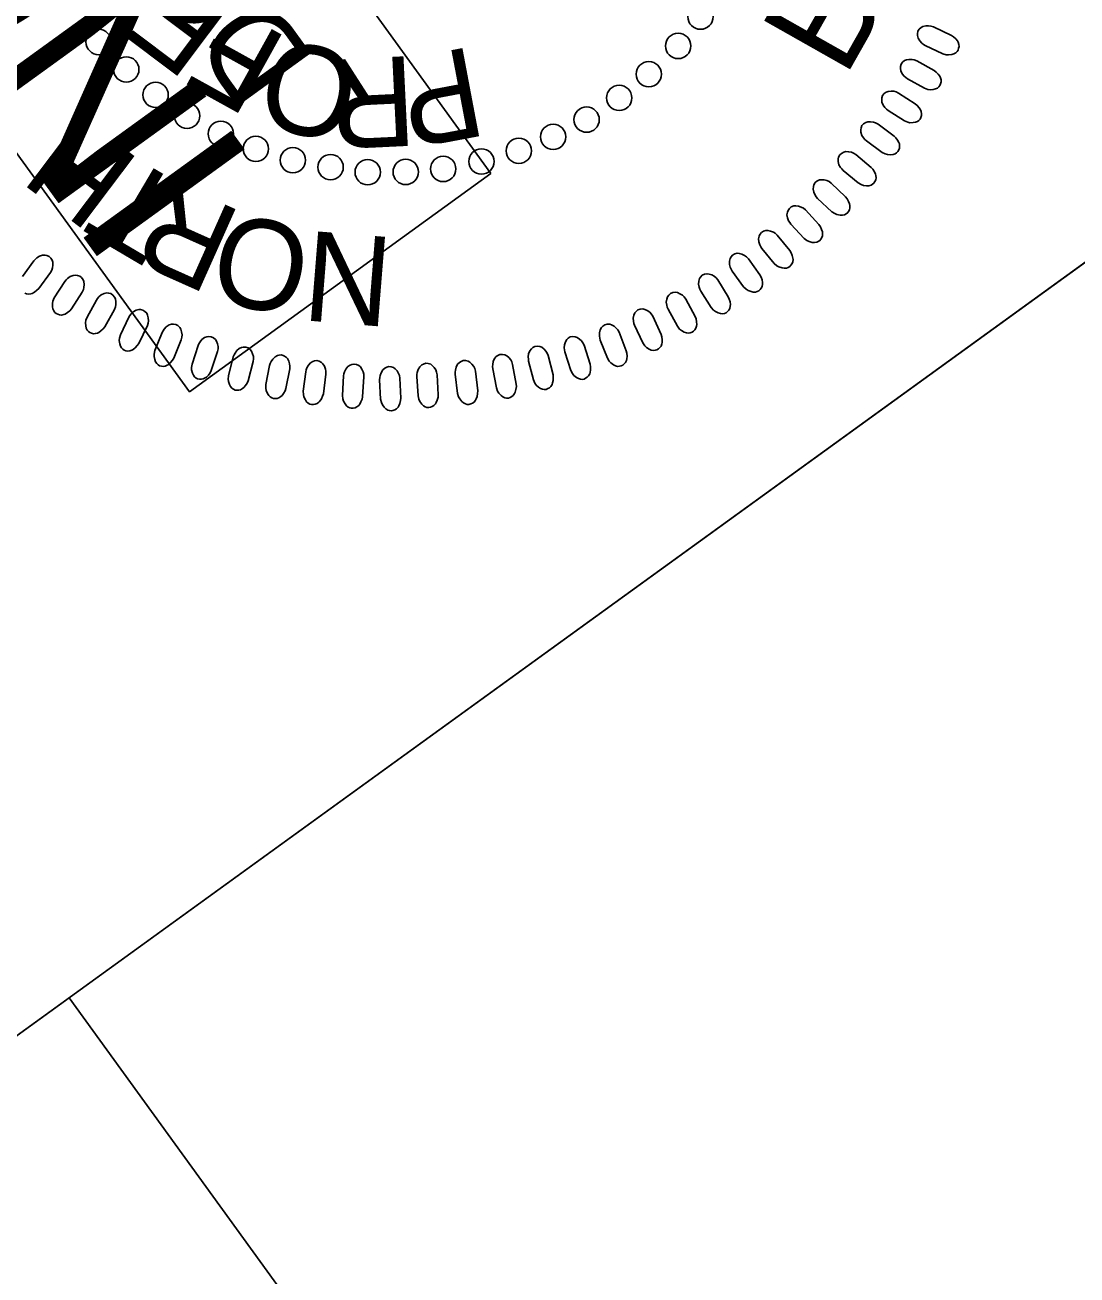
# Model space of a CAD drawing. Extents: x 474248 to 476123, y 501895 to 503900.
# Drawn here: x 474424.9 to 474491.3, y 503102.6 to 503181.5 of the extents above; entities that cross this region are included whole.
import ezdxf

# ---------------------------------------------------------------- set-up
doc = ezdxf.new("R2010")
doc.units = 0
for name, color, linetype in [('Prop Grid Mask', 7, 'Continuous'), ('Scratch_Level_5', 7, 'Continuous'), ('Sheet Layout Plan Border', 7, 'Continuous'), ('Sheet PE Seal Cell', 7, 'Continuous'), ('Sheet Plan CELL', 7, 'Continuous'), ('Sheet Sticker Incomplete CELL', 7, 'Continuous')]:
    doc.layers.add(name, color=color, linetype=linetype)

msp = doc.modelspace()

# ---------------------------------------------------------------- linework, layer by layer
at = {"layer": 'Prop Grid Mask'}
msp.add_lwpolyline([(474393.918, 503095.623), (474486.211, 502968.161), (474519.992, 502992.621), (474427.7, 503120.083)], close=True, dxfattribs=at)
at = {"layer": 'Scratch_Level_5'}
msp.add_lwpolyline([(474627.913, 502772.461), (474393.918, 503095.623), (474534.481, 503197.416), (474417.163, 503359.44), (475062.239, 503826.524), (475162.267, 503688.379), (475227.085, 503735.313), (475493.156, 503367.85)], close=True, dxfattribs=at)
at = {"layer": 'Sheet Layout Plan Border'}
msp.add_lwpolyline([(475148.793, 502314.888), (475799.674, 502786.065), (475874.954, 502840.561), (475397.529, 503499.918), (475353.895, 503468.323), (475265.228, 503590.778), (475283.66, 503604.124), (475199.913, 503719.785), (475161.571, 503692.033), (475161.571, 503692.033), (475161.571, 503692.033), (475161.571, 503692.033), (475161.571, 503692.033), (475063.524, 503827.461), (474417.163, 503359.44), (474534.481, 503197.416), (474393.908, 503095.616), (475024.421, 502224.855)], close=True, dxfattribs=at)
at = {"layer": 'Sheet PE Seal Cell'}
for points in [[(474481.763, 503180.24), (474482.873, 503179.715), (474483.086, 503179.655), (474483.235, 503179.643), (474483.436, 503179.671), (474483.578, 503179.713), (474483.697, 503179.78), (474483.778, 503179.857), (474483.844, 503179.95), (474483.874, 503180.06), (474483.898, 503180.181), (474483.889, 503180.301), (474483.843, 503180.438), (474483.797, 503180.527), (474483.69, 503180.651), (474483.553, 503180.782), (474483.419, 503180.871), (474482.286, 503181.415), (474482.123, 503181.467), (474481.978, 503181.486), (474481.795, 503181.473), (474481.622, 503181.431), (474481.507, 503181.378), (474481.387, 503181.261), (474481.304, 503181.134), (474481.277, 503180.982), (474481.277, 503180.866), (474481.312, 503180.709), (474481.415, 503180.529), (474481.548, 503180.391), (474481.653, 503180.309)], [(474480.637, 503178.131), (474481.711, 503177.538), (474481.921, 503177.465), (474482.069, 503177.443), (474482.271, 503177.46), (474482.415, 503177.491), (474482.539, 503177.551), (474482.624, 503177.623), (474482.696, 503177.712), (474482.732, 503177.819), (474482.764, 503177.939), (474482.762, 503178.059), (474482.725, 503178.199), (474482.685, 503178.29), (474482.586, 503178.421), (474482.458, 503178.56), (474482.329, 503178.657), (474481.233, 503179.272), (474481.073, 503179.334), (474480.93, 503179.362), (474480.747, 503179.36), (474480.57, 503179.33), (474480.453, 503179.283), (474480.325, 503179.175), (474480.235, 503179.053), (474480.198, 503178.904), (474480.191, 503178.787), (474480.216, 503178.628), (474480.308, 503178.442), (474480.432, 503178.296), (474480.531, 503178.207)], [(474479.416, 503176.137), (474480.45, 503175.477), (474480.656, 503175.39), (474480.801, 503175.359), (474481.004, 503175.363), (474481.149, 503175.386), (474481.277, 503175.438), (474481.366, 503175.504), (474481.444, 503175.588), (474481.487, 503175.693), (474481.526, 503175.81), (474481.532, 503175.93), (474481.504, 503176.072), (474481.469, 503176.166), (474481.379, 503176.303), (474481.26, 503176.449), (474481.137, 503176.554), (474480.082, 503177.236), (474479.926, 503177.309), (474479.785, 503177.346), (474479.602, 503177.356), (474479.424, 503177.336), (474479.304, 503177.297), (474479.169, 503177.197), (474479.072, 503177.081), (474479.026, 503176.935), (474479.012, 503176.819), (474479.027, 503176.658), (474479.107, 503176.467), (474479.221, 503176.313), (474479.315, 503176.219)], [(474478.049, 503174.21), (474479.04, 503173.487), (474479.239, 503173.388), (474479.382, 503173.347), (474479.586, 503173.338), (474479.732, 503173.352), (474479.862, 503173.396), (474479.956, 503173.457), (474480.038, 503173.535), (474480.087, 503173.638), (474480.134, 503173.752), (474480.148, 503173.872), (474480.128, 503174.015), (474480.1, 503174.11), (474480.018, 503174.253), (474479.908, 503174.407), (474479.793, 503174.519), (474478.782, 503175.266), (474478.632, 503175.347), (474478.492, 503175.394), (474478.311, 503175.415), (474478.132, 503175.407), (474478.01, 503175.376), (474477.87, 503175.284), (474477.765, 503175.175), (474477.709, 503175.031), (474477.688, 503174.917), (474477.693, 503174.756), (474477.76, 503174.559), (474477.865, 503174.399), (474477.953, 503174.298)], [(474476.582, 503172.341), (474477.526, 503171.557), (474477.718, 503171.446), (474477.859, 503171.396), (474478.061, 503171.374), (474478.208, 503171.379), (474478.341, 503171.415), (474478.438, 503171.47), (474478.525, 503171.543), (474478.581, 503171.642), (474478.634, 503171.753), (474478.656, 503171.871), (474478.646, 503172.016), (474478.623, 503172.113), (474478.551, 503172.26), (474478.45, 503172.421), (474478.342, 503172.54), (474477.381, 503173.349), (474477.236, 503173.44), (474477.1, 503173.494), (474476.92, 503173.527), (474476.741, 503173.531), (474476.618, 503173.507), (474476.471, 503173.424), (474476.36, 503173.322), (474476.295, 503173.182), (474476.267, 503173.069), (474476.262, 503172.908), (474476.316, 503172.708), (474476.411, 503172.54), (474476.492, 503172.435)], [(474474.967, 503170.58), (474475.859, 503169.738), (474476.045, 503169.615), (474476.182, 503169.556), (474476.383, 503169.522), (474476.529, 503169.517), (474476.664, 503169.544), (474476.764, 503169.593), (474476.856, 503169.661), (474476.918, 503169.756), (474476.978, 503169.864), (474477.007, 503169.981), (474477.006, 503170.126), (474476.989, 503170.224), (474476.927, 503170.376), (474476.837, 503170.542), (474476.736, 503170.668), (474475.827, 503171.535), (474475.688, 503171.635), (474475.556, 503171.699), (474475.379, 503171.742), (474475.2, 503171.757), (474475.075, 503171.741), (474474.924, 503171.668), (474474.807, 503171.572), (474474.733, 503171.437), (474474.698, 503171.326), (474474.683, 503171.165), (474474.725, 503170.962), (474474.809, 503170.789), (474474.883, 503170.68)], [(474473.279, 503168.946), (474474.117, 503168.05), (474474.294, 503167.916), (474474.427, 503167.848), (474474.625, 503167.802), (474474.771, 503167.788), (474474.908, 503167.806), (474475.011, 503167.849), (474475.107, 503167.911), (474475.175, 503168.002), (474475.242, 503168.105), (474475.278, 503168.22), (474475.285, 503168.365), (474475.275, 503168.464), (474475.222, 503168.619), (474475.143, 503168.791), (474475.05, 503168.923), (474474.197, 503169.846), (474474.065, 503169.954), (474473.937, 503170.026), (474473.763, 503170.081), (474473.586, 503170.107), (474473.46, 503170.099), (474473.304, 503170.035), (474473.182, 503169.947), (474473.1, 503169.816), (474473.057, 503169.708), (474473.032, 503169.548), (474473.061, 503169.343), (474473.135, 503169.166), (474473.201, 503169.051)], [(474471.447, 503167.416), (474472.227, 503166.469), (474472.395, 503166.324), (474472.524, 503166.249), (474472.719, 503166.189), (474472.864, 503166.166), (474473.001, 503166.176), (474473.107, 503166.212), (474473.206, 503166.269), (474473.279, 503166.355), (474473.353, 503166.455), (474473.396, 503166.566), (474473.413, 503166.71), (474473.409, 503166.81), (474473.365, 503166.968), (474473.297, 503167.145), (474473.214, 503167.282), (474472.42, 503168.257), (474472.294, 503168.373), (474472.171, 503168.452), (474472, 503168.518), (474471.825, 503168.555), (474471.7, 503168.555), (474471.54, 503168.501), (474471.412, 503168.421), (474471.322, 503168.295), (474471.273, 503168.19), (474471.239, 503168.033), (474471.254, 503167.826), (474471.316, 503167.644), (474471.376, 503167.525)], [(474469.568, 503165.991), (474470.287, 503164.997), (474470.446, 503164.842), (474470.57, 503164.758), (474470.76, 503164.687), (474470.903, 503164.655), (474471.041, 503164.657), (474471.149, 503164.686), (474471.252, 503164.735), (474471.33, 503164.817), (474471.41, 503164.911), (474471.46, 503165.021), (474471.486, 503165.163), (474471.488, 503165.263), (474471.455, 503165.424), (474471.398, 503165.604), (474471.322, 503165.746), (474470.592, 503166.769), (474470.475, 503166.893), (474470.356, 503166.98), (474470.19, 503167.056), (474470.017, 503167.104), (474469.892, 503167.112), (474469.729, 503167.068), (474469.596, 503166.997), (474469.499, 503166.876), (474469.444, 503166.775), (474469.398, 503166.62), (474469.401, 503166.412), (474469.452, 503166.227), (474469.504, 503166.105)], [(474427.415, 503165.326), (474426.755, 503164.292), (474426.669, 503164.086), (474426.637, 503163.941), (474426.641, 503163.737), (474426.664, 503163.593), (474426.716, 503163.466), (474426.783, 503163.375), (474426.867, 503163.299), (474426.972, 503163.255), (474427.089, 503163.216), (474427.209, 503163.21), (474427.351, 503163.238), (474427.444, 503163.273), (474427.582, 503163.363), (474427.728, 503163.482), (474427.833, 503163.604), (474428.515, 503164.66), (474428.587, 503164.815), (474428.624, 503164.957), (474428.634, 503165.14), (474428.615, 503165.318), (474428.576, 503165.438), (474428.476, 503165.573), (474428.36, 503165.669), (474428.213, 503165.716), (474428.098, 503165.73), (474427.937, 503165.715), (474427.745, 503165.637), (474427.591, 503165.52), (474427.497, 503165.427)], [(474467.587, 503164.718), (474468.242, 503163.681), (474468.391, 503163.515), (474468.51, 503163.425), (474468.695, 503163.341), (474468.836, 503163.3), (474468.973, 503163.293), (474469.083, 503163.315), (474469.189, 503163.358), (474469.272, 503163.435), (474469.358, 503163.525), (474469.415, 503163.63), (474469.45, 503163.771), (474469.458, 503163.87), (474469.435, 503164.033), (474469.39, 503164.216), (474469.323, 503164.363), (474468.658, 503165.43), (474468.549, 503165.561), (474468.436, 503165.655), (474468.275, 503165.742), (474468.106, 503165.8), (474467.981, 503165.816), (474467.816, 503165.782), (474467.679, 503165.719), (474467.575, 503165.606), (474467.512, 503165.508), (474467.458, 503165.356), (474467.448, 503165.149), (474467.486, 503164.96), (474467.531, 503164.835)], [(474429.412, 503164.158), (474428.819, 503163.084), (474428.746, 503162.875), (474428.724, 503162.727), (474428.739, 503162.524), (474428.772, 503162.381), (474428.831, 503162.257), (474428.904, 503162.171), (474428.992, 503162.1), (474429.1, 503162.063), (474429.219, 503162.031), (474429.339, 503162.033), (474429.48, 503162.07), (474429.57, 503162.111), (474429.702, 503162.209), (474429.841, 503162.338), (474429.938, 503162.466), (474430.551, 503163.562), (474430.614, 503163.722), (474430.642, 503163.866), (474430.64, 503164.049), (474430.61, 503164.226), (474430.564, 503164.342), (474430.455, 503164.47), (474430.334, 503164.56), (474430.184, 503164.597), (474430.068, 503164.604), (474429.909, 503164.579), (474429.722, 503164.488), (474429.576, 503164.364), (474429.487, 503164.264)], [(474465.521, 503163.575), (474466.11, 503162.499), (474466.247, 503162.325), (474466.36, 503162.227), (474466.54, 503162.132), (474466.678, 503162.082), (474466.815, 503162.066), (474466.926, 503162.082), (474467.034, 503162.118), (474467.122, 503162.189), (474467.213, 503162.273), (474467.276, 503162.376), (474467.32, 503162.514), (474467.334, 503162.612), (474467.321, 503162.776), (474467.288, 503162.962), (474467.231, 503163.113), (474466.634, 503164.219), (474466.533, 503164.357), (474466.427, 503164.457), (474466.272, 503164.554), (474466.106, 503164.623), (474465.982, 503164.646), (474465.816, 503164.624), (474465.675, 503164.569), (474465.563, 503164.462), (474465.495, 503164.368), (474465.432, 503164.22), (474465.408, 503164.014), (474465.436, 503163.824), (474465.472, 503163.696)], [(474431.455, 503163.066), (474430.93, 503161.956), (474430.87, 503161.742), (474430.857, 503161.594), (474430.886, 503161.392), (474430.927, 503161.252), (474430.994, 503161.132), (474431.072, 503161.051), (474431.165, 503160.985), (474431.274, 503160.955), (474431.396, 503160.931), (474431.516, 503160.94), (474431.653, 503160.986), (474431.741, 503161.032), (474431.866, 503161.138), (474431.997, 503161.275), (474432.086, 503161.41), (474432.63, 503162.543), (474432.682, 503162.705), (474432.701, 503162.851), (474432.688, 503163.033), (474432.646, 503163.208), (474432.593, 503163.321), (474432.476, 503163.443), (474432.35, 503163.524), (474432.198, 503163.552), (474432.082, 503163.552), (474431.924, 503163.516), (474431.744, 503163.414), (474431.606, 503163.281), (474431.524, 503163.176)], [(474463.4, 503162.559), (474463.92, 503161.448), (474464.046, 503161.265), (474464.153, 503161.16), (474464.327, 503161.054), (474464.461, 503160.996), (474464.597, 503160.971), (474464.708, 503160.98), (474464.818, 503161.009), (474464.911, 503161.075), (474465.007, 503161.153), (474465.076, 503161.251), (474465.128, 503161.386), (474465.149, 503161.483), (474465.147, 503161.648), (474465.125, 503161.836), (474465.077, 503161.989), (474464.551, 503163.131), (474464.459, 503163.275), (474464.359, 503163.382), (474464.21, 503163.488), (474464.05, 503163.568), (474463.928, 503163.598), (474463.76, 503163.586), (474463.616, 503163.541), (474463.497, 503163.441), (474463.424, 503163.352), (474463.351, 503163.208), (474463.315, 503163.004), (474463.33, 503162.812), (474463.358, 503162.682)], [(474433.563, 503162.101), (474433.109, 503160.961), (474433.062, 503160.743), (474433.059, 503160.595), (474433.1, 503160.396), (474433.15, 503160.258), (474433.225, 503160.143), (474433.307, 503160.066), (474433.404, 503160.007), (474433.516, 503159.983), (474433.638, 503159.967), (474433.757, 503159.984), (474433.891, 503160.038), (474433.977, 503160.09), (474434.095, 503160.204), (474434.216, 503160.349), (474434.297, 503160.489), (474434.768, 503161.653), (474434.81, 503161.819), (474434.82, 503161.966), (474434.796, 503162.147), (474434.743, 503162.318), (474434.683, 503162.428), (474434.559, 503162.542), (474434.427, 503162.615), (474434.274, 503162.634), (474434.158, 503162.626), (474434.003, 503162.581), (474433.829, 503162.467), (474433.7, 503162.325), (474433.625, 503162.216)], [(474461.24, 503161.627), (474461.69, 503160.485), (474461.805, 503160.295), (474461.904, 503160.183), (474462.071, 503160.067), (474462.201, 503160), (474462.335, 503159.967), (474462.447, 503159.969), (474462.559, 503159.991), (474462.656, 503160.05), (474462.756, 503160.122), (474462.832, 503160.216), (474462.892, 503160.347), (474462.919, 503160.443), (474462.927, 503160.608), (474462.916, 503160.796), (474462.879, 503160.953), (474462.426, 503162.125), (474462.343, 503162.275), (474462.25, 503162.388), (474462.108, 503162.503), (474461.953, 503162.592), (474461.833, 503162.631), (474461.665, 503162.63), (474461.518, 503162.593), (474461.394, 503162.501), (474461.315, 503162.416), (474461.233, 503162.277), (474461.184, 503162.076), (474461.187, 503161.884), (474461.207, 503161.752)], [(474435.833, 503161.275), (474435.452, 503160.109), (474435.419, 503159.889), (474435.425, 503159.74), (474435.479, 503159.544), (474435.538, 503159.409), (474435.619, 503159.299), (474435.706, 503159.228), (474435.807, 503159.175), (474435.919, 503159.158), (474436.042, 503159.15), (474436.16, 503159.174), (474436.291, 503159.236), (474436.373, 503159.293), (474436.483, 503159.415), (474436.596, 503159.567), (474436.667, 503159.711), (474437.065, 503160.903), (474437.096, 503161.072), (474437.097, 503161.219), (474437.061, 503161.398), (474436.998, 503161.565), (474436.931, 503161.672), (474436.8, 503161.777), (474436.664, 503161.842), (474436.509, 503161.851), (474436.395, 503161.836), (474436.243, 503161.781), (474436.076, 503161.657), (474435.956, 503161.507), (474435.888, 503161.393)], [(474459, 503160.874), (474459.377, 503159.707), (474459.48, 503159.51), (474459.572, 503159.392), (474459.731, 503159.265), (474459.858, 503159.191), (474459.989, 503159.15), (474460.1, 503159.144), (474460.213, 503159.16), (474460.314, 503159.213), (474460.419, 503159.278), (474460.499, 503159.367), (474460.569, 503159.494), (474460.601, 503159.589), (474460.619, 503159.752), (474460.621, 503159.94), (474460.593, 503160.099), (474460.215, 503161.298), (474460.141, 503161.452), (474460.055, 503161.571), (474459.921, 503161.695), (474459.772, 503161.793), (474459.654, 503161.841), (474459.487, 503161.849), (474459.338, 503161.822), (474459.208, 503161.738), (474459.125, 503161.658), (474459.033, 503161.525), (474458.972, 503161.326), (474458.963, 503161.135), (474458.975, 503161.002)], [(474438.061, 503160.566), (474437.754, 503159.378), (474437.735, 503159.157), (474437.75, 503159.009), (474437.817, 503158.817), (474437.883, 503158.686), (474437.971, 503158.58), (474438.063, 503158.516), (474438.167, 503158.469), (474438.281, 503158.46), (474438.403, 503158.459), (474438.52, 503158.49), (474438.646, 503158.561), (474438.724, 503158.623), (474438.827, 503158.751), (474438.93, 503158.909), (474438.992, 503159.059), (474439.314, 503160.273), (474439.334, 503160.443), (474439.326, 503160.589), (474439.279, 503160.766), (474439.205, 503160.929), (474439.131, 503161.031), (474438.994, 503161.128), (474438.854, 503161.185), (474438.7, 503161.183), (474438.586, 503161.162), (474438.438, 503161.097), (474438.28, 503160.963), (474438.17, 503160.806), (474438.108, 503160.688)], [(474440.356, 503160.021), (474440.124, 503158.816), (474440.119, 503158.594), (474440.143, 503158.446), (474440.222, 503158.259), (474440.296, 503158.133), (474440.391, 503158.033), (474440.487, 503157.974), (474440.593, 503157.933), (474440.707, 503157.932), (474440.83, 503157.939), (474440.944, 503157.977), (474441.066, 503158.056), (474441.14, 503158.122), (474441.234, 503158.257), (474441.326, 503158.422), (474441.379, 503158.573), (474441.624, 503159.807), (474441.634, 503159.977), (474441.616, 503160.122), (474441.559, 503160.296), (474441.475, 503160.455), (474441.395, 503160.552), (474441.252, 503160.64), (474441.108, 503160.688), (474440.955, 503160.677), (474440.842, 503160.648), (474440.698, 503160.574), (474440.549, 503160.431), (474440.449, 503160.267), (474440.395, 503160.145)], [(474454.446, 503159.818), (474454.674, 503158.613), (474454.751, 503158.404), (474454.828, 503158.276), (474454.97, 503158.131), (474455.086, 503158.041), (474455.211, 503157.983), (474455.321, 503157.963), (474455.435, 503157.965), (474455.541, 503158.005), (474455.653, 503158.057), (474455.745, 503158.134), (474455.829, 503158.252), (474455.873, 503158.342), (474455.911, 503158.501), (474455.937, 503158.689), (474455.93, 503158.85), (474455.704, 503160.087), (474455.65, 503160.248), (474455.58, 503160.377), (474455.463, 503160.517), (474455.326, 503160.634), (474455.217, 503160.694), (474455.051, 503160.724), (474454.9, 503160.716), (474454.761, 503160.649), (474454.667, 503160.58), (474454.561, 503160.459), (474454.475, 503160.27), (474454.442, 503160.082), (474454.437, 503159.948)], [(474456.713, 503160.3), (474457.016, 503159.111), (474457.107, 503158.908), (474457.191, 503158.785), (474457.342, 503158.648), (474457.463, 503158.566), (474457.591, 503158.517), (474457.703, 503158.504), (474457.817, 503158.512), (474457.92, 503158.559), (474458.029, 503158.618), (474458.115, 503158.701), (474458.192, 503158.824), (474458.231, 503158.916), (474458.259, 503159.078), (474458.272, 503159.266), (474458.255, 503159.427), (474457.952, 503160.646), (474457.888, 503160.804), (474457.81, 503160.929), (474457.684, 503161.061), (474457.541, 503161.169), (474457.427, 503161.223), (474457.26, 503161.242), (474457.111, 503161.224), (474456.976, 503161.149), (474456.886, 503161.074), (474456.787, 503160.947), (474456.714, 503160.753), (474456.693, 503160.562), (474456.696, 503160.429)], [(474442.634, 503159.618), (474442.478, 503158.402), (474442.488, 503158.179), (474442.521, 503158.034), (474442.611, 503157.851), (474442.693, 503157.73), (474442.795, 503157.637), (474442.893, 503157.584), (474443.002, 503157.55), (474443.115, 503157.555), (474443.238, 503157.57), (474443.349, 503157.616), (474443.466, 503157.701), (474443.535, 503157.773), (474443.622, 503157.913), (474443.703, 503158.083), (474443.747, 503158.238), (474443.914, 503159.484), (474443.913, 503159.655), (474443.886, 503159.799), (474443.817, 503159.969), (474443.724, 503160.121), (474443.638, 503160.213), (474443.49, 503160.293), (474443.344, 503160.331), (474443.191, 503160.31), (474443.081, 503160.275), (474442.942, 503160.192), (474442.801, 503160.039), (474442.712, 503159.869), (474442.666, 503159.745)], [(474445.028, 503159.359), (474444.948, 503158.135), (474444.972, 503157.914), (474445.014, 503157.771), (474445.115, 503157.594), (474445.205, 503157.479), (474445.312, 503157.392), (474445.414, 503157.346), (474445.525, 503157.318), (474445.638, 503157.331), (474445.759, 503157.353), (474445.867, 503157.405), (474445.978, 503157.498), (474446.043, 503157.574), (474446.12, 503157.719), (474446.191, 503157.895), (474446.224, 503158.052), (474446.313, 503159.306), (474446.302, 503159.476), (474446.266, 503159.618), (474446.186, 503159.784), (474446.084, 503159.93), (474445.991, 503160.016), (474445.839, 503160.086), (474445.692, 503160.115), (474445.539, 503160.085), (474445.432, 503160.042), (474445.298, 503159.951), (474445.168, 503159.79), (474445.089, 503159.615), (474445.051, 503159.487)], [(474447.301, 503159.122), (474447.365, 503157.898), (474447.415, 503157.68), (474447.474, 503157.544), (474447.595, 503157.38), (474447.698, 503157.276), (474447.814, 503157.203), (474447.92, 503157.168), (474448.034, 503157.154), (474448.145, 503157.18), (474448.262, 503157.217), (474448.364, 503157.281), (474448.463, 503157.386), (474448.519, 503157.469), (474448.578, 503157.622), (474448.628, 503157.805), (474448.642, 503157.965), (474448.583, 503159.22), (474448.552, 503159.389), (474448.499, 503159.525), (474448.401, 503159.68), (474448.282, 503159.813), (474448.18, 503159.888), (474448.021, 503159.939), (474447.871, 503159.951), (474447.723, 503159.904), (474447.622, 503159.848), (474447.5, 503159.742), (474447.39, 503159.567), (474447.332, 503159.384), (474447.309, 503159.253)], [(474449.651, 503159.325), (474449.726, 503158.101), (474449.777, 503157.884), (474449.837, 503157.748), (474449.959, 503157.585), (474450.063, 503157.481), (474450.18, 503157.409), (474450.287, 503157.375), (474450.4, 503157.362), (474450.511, 503157.389), (474450.628, 503157.426), (474450.729, 503157.492), (474450.827, 503157.598), (474450.883, 503157.681), (474450.941, 503157.835), (474450.989, 503158.018), (474451.002, 503158.178), (474450.933, 503159.433), (474450.9, 503159.601), (474450.847, 503159.738), (474450.748, 503159.891), (474450.627, 503160.024), (474450.526, 503160.098), (474450.365, 503160.148), (474450.214, 503160.158), (474450.068, 503160.11), (474449.966, 503160.054), (474449.845, 503159.946), (474449.737, 503159.77), (474449.68, 503159.587), (474449.658, 503159.455)], [(474452.076, 503159.471), (474452.227, 503158.253), (474452.291, 503158.04), (474452.36, 503157.908), (474452.492, 503157.754), (474452.603, 503157.657), (474452.723, 503157.591), (474452.832, 503157.565), (474452.946, 503157.559), (474453.054, 503157.593), (474453.17, 503157.637), (474453.266, 503157.709), (474453.357, 503157.821), (474453.407, 503157.907), (474453.456, 503158.064), (474453.493, 503158.25), (474453.495, 503158.411), (474453.348, 503159.659), (474453.305, 503159.824), (474453.243, 503159.957), (474453.134, 503160.105), (474453.006, 503160.23), (474452.899, 503160.297), (474452.736, 503160.337), (474452.585, 503160.338), (474452.442, 503160.28), (474452.344, 503160.218), (474452.23, 503160.103), (474452.133, 503159.92), (474452.088, 503159.734), (474452.074, 503159.601)]]:
    msp.add_lwpolyline(points, close=True, dxfattribs=at)
msp.add_lwpolyline([(474424.891, 503164.59), (474425.005, 503164.545), (474425.124, 503164.531), (474425.268, 503164.55), (474425.363, 503164.579), (474425.506, 503164.66), (474425.66, 503164.77), (474425.773, 503164.886), (474426.519, 503165.896), (474426.6, 503166.047), (474426.646, 503166.186), (474426.668, 503166.368), (474426.66, 503166.546), (474426.628, 503166.668), (474426.537, 503166.809), (474426.428, 503166.913), (474426.284, 503166.969), (474426.169, 503166.991), (474426.008, 503166.985), (474425.812, 503166.918), (474425.652, 503166.813), (474425.551, 503166.726), (474425.463, 503166.63), (474424.74, 503165.639)], dxfattribs=at)
for centre in [(474467.569, 503182.064), (474429.554, 503180.459), (474466.158, 503180.208), (474431.3, 503178.724), (474464.303, 503178.423), (474433.152, 503177.116), (474462.436, 503176.926), (474435.137, 503175.8), (474460.375, 503175.553), (474437.271, 503174.661), (474458.261, 503174.465), (474439.485, 503173.707), (474456.094, 503173.586), (474441.823, 503172.991), (474444.205, 503172.552), (474451.318, 503172.44), (474453.732, 503172.909), (474446.55, 503172.234), (474448.949, 503172.249)]:
    msp.add_circle(centre, 0.801, dxfattribs=at)
at = {"layer": 'Sheet Plan CELL'}
for points in [[(476006.781, 502658.499), (475156.352, 502042.692), (474393.908, 503095.616), (474515.447, 503183.634), (474398.139, 503345.665), (475127.058, 503873.458)], [(474424.343, 503117.653), (474365.666, 503198.69), (474456.797, 503264.676), (474515.447, 503183.634)]]:
    msp.add_lwpolyline(points, close=True, dxfattribs=at)
at = {"layer": 'Sheet Sticker Incomplete CELL'}
msp.add_lwpolyline([(474454.332, 503172.147), (474435.298, 503158.364), (474349.086, 503277.429), (474368.12, 503291.211)], close=True, dxfattribs=at)

# ---------------------------------------------------------------- texts
at = {"layer": 'Sheet PE Seal Cell'}
for s, height, rotation, p in [('E', 5.669, 143.07246, (474438.416, 503182.477)), ('B', 6.236, 60.49354, (474476.684, 503178.136)), ('F', 5.669, 151.01226, (474441.65, 503180.633)), ('O', 5.669, 166.89186, (474446.361, 503179.479)), ('R', 5.669, 182.77145, (474449.428, 503179.584)), ('P', 5.669, 190.71125, (474453.141, 503180.19)), ('H', 5.669, 142.95959, (474432.316, 503172.88)), ('T', 5.669, 149.44894, (474435.322, 503171.132)), ('R', 5.669, 155.9383, (474438.765, 503169.648)), ('O', 5.669, 168.91701, (474443.256, 503168.609)), ('N', 5.669, 175.40637, (474448.261, 503168.1))]:
    msp.add_text(s, height=height, rotation=rotation, dxfattribs=at).set_placement(p)
at = {"layer": 'Sheet Sticker Incomplete CELL'}
for s, height, p in [('INCOMPLETE PLANS', 11.52, (474439.607, 503172.534)), ('DO NOT USE FOR R/W ACQUISITION', 5.76, (474443.33, 503179.242))]:
    msp.add_text(s, height=height, rotation=125.90742, dxfattribs=at).set_placement(p)

doc.saveas('drawing.dxf')
